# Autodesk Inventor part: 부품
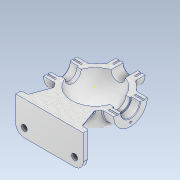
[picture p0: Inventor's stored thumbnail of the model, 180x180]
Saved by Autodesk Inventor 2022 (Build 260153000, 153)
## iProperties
Created: 2024-04
Part Number: 부품
Material: 알루미늄 6061
Document SubType Name: Modeling
Designer: admin
Density: 2.7 g/cm^3
Appearance: 알루미늄 - 평지
Mass: 2352.45 g
Surface Area: 1021.09 cm^2
Volume: 871.277 cm^3
Author: admin
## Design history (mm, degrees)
sketch "스케치1"
  geometry: L1 (-154.368, 0)-(181.043, 0) reference; L2 (0, -46.839)-(0, 70.807) reference; L3 (-65, 31)-(65, 31); L4 (65, 31)-(65, 0); L5 (-65, 0)-(-65, 31); L6 (-65, 31)-(60.942, -29.064); L7 (65, 31)-(-62.972, -30.033); L8 (-106.452, 0)-(133.128, 0); A1 r 54 centre (0, 0) between (54, 0) and (-54, 0); 3 further points
  constraints: 12 end point, 8 point on line, 2 point on circle, 1 centre point, 1 coincident, 1 horizontal, 1 parallel, 1 perpendicular, 1 other
  dimensions: "d0" = 108 diameter of A1; "d1" = 130 distance of L3.start L3.end; "d2" = 62 diameter of L3 L8
revolve "회전1" stored, may be unused: angle "d3" = 360 deg
node "작업 평면1"
sketch "스케치3"
  geometry: L1 (-62.5, -62.5)-(62.5, -62.5); L2 (62.5, -62.5)-(62.5, 62.5); L3 (62.5, 62.5)-(-62.5, 62.5); L4 (-62.5, 62.5)-(-62.5, -62.5); L5 (-62.5, -62.5)-(62.5, 62.5); L6 (62.5, -62.5)-(-62.5, 62.5); 1 further point
  constraints: 12 end point, 2 midpoint, 2 parallel, 1 horizontal, 1 perpendicular
  dimensions: "d5" = 125 distance of L1.start L1.end; "d6" = 125 distance of L1.end L2.end
extrude "돌출1" join sketch "스케치3" distance "d7" = 10; taper "d8" = 0 deg
fillet "모깎기1" dims "d10" = 16
sketch "스케치5"
  geometry: L1 (-62.5, -46.5)-(-62.5, 46.5) reference; L2 (-46.5, 62.5)-(46.5, 62.5) reference; L3 (62.5, 46.5)-(62.5, -46.5) reference; L4 (46.5, -62.5)-(-46.5, -62.5) reference; L5 (0, -92.139)-(0, 92.139) reference; L6 (92.139, 0)-(-92.139, 0) reference; L7 (-50.5, 4)-(50.5, 4); L8 (50.5, 4)-(50.5, -4); L9 (50.5, -4)-(-50.5, -4); L10 (-50.5, -4)-(-50.5, 4); C1 r 5.5 at (-46.5, 46.5); C2 r 5.5 at (46.5, 46.5); C3 r 5.5 at (46.5, -46.5); C4 r 5.5 at (-46.5, -46.5); A1 r 16 centre (-46.5, -46.5) between (-62.5, -46.5) and (-46.5, -62.5) reference; A2 r 16 centre (-46.5, 46.5) between (-46.5, 62.5) and (-62.5, 46.5) reference; A3 r 16 centre (46.5, 46.5) between (62.5, 46.5) and (46.5, 62.5) reference; A4 r 16 centre (46.5, -46.5) between (46.5, -62.5) and (62.5, -46.5) reference; 1 further point
  constraints: 8 end point, 4 centre point, 4 coincident, 3 equal radius, 2 parallel, 1 horizontal, 1 perpendicular, 2 other
  dimensions: "d11" = 11 diameter of C1; "d12" = 8 distance of L7.end L8.end; "d14" = 12 distance between parallel lines of L3 L8
extrude "돌출2" join sketch "스케치5" stored distance "d15" = 10; taper "d16" = 0 deg
feature "면 기울기1" dims angle "d17" = 20 deg
feature "면 기울기2" dims angle "d18" = 20 deg
sketch "스케치7"
  geometry: L1 (-50.5, 75)-(-36.114, 35.475); L2 (-62.5, 85)-(-62.5, 75) reference; L3 (-46.5, 75)-(-62.5, 75) reference; 1 further point
  constraints: 2 end point, 1 point on line
  dimensions: "d19" = 12 distance from line of L2 L1.start; "d20" = 110 deg angle of L3 L1
feature "리브1" sketch "스케치7" dims "d21" = 1, "d22" = 8, "d23" = 0, "d24" = 0, "d25" = 1, "d26" = 1
node "작업 평면2"
sketch "스케치8"
  geometry: C1 r 27 at (0, 0); 1 further point
  constraints: 1 centre point, 1 coincident
  dimensions: "d28" = 54 diameter of C1
extrude "돌출3" join sketch "스케치8" stored distance "d29" = 10; taper "d30" = 0 deg
sketch "스케치9"
  geometry: L1 (0, -87.5)-(0, 87.5) reference; L2 (91, 0)-(-91, 0) reference; C1 r 27 at (0, 0) reference; A1 r 20 centre (0, 0) between (20, 0) and (0, 20); 3 further points
  constraints: 4 point on circle, 4 point on line, 1 centre point, 1 coincident
  dimensions: "d31" = 40 diameter of A1
hole "구멍1" sketch "스케치9" at (20, 0), (0, 20), (-20, 0), (0, -20) diameter "d32" = 3.242; stored, may be unused: countersink angle "d36" = 90 deg, drill point angle "d38" = 118 deg; dims "d33" = 9, "d34" = 4, "d35" = 2, "d37" = 11
node "작업 평면3"
node "작업 평면4"
node "작업 평면5"
sketch "스케치12"
  geometry: L1 (0, -75.6)-(0, 75.6) reference; L2 (-75.6, 0)-(75.6, 0) reference; A1 r 24 centre (0, 0) between (-24, 0) and (0, 24); 3 further points
  constraints: 4 point on circle, 4 point on line, 1 centre point, 1 coincident
  dimensions: "d46" = 48 diameter of A1
hole "구멍2" sketch "스케치12" at (-24, 0), (0, 24), (24, 0), (0, -24) diameter "d47" = 3.242; stored, may be unused: countersink angle "d51" = 90 deg, drill point angle "d53" = 118 deg; dims "d48" = 12, "d49" = 4, "d50" = 2, "d52" = 15
sketch "스케치13"
  geometry: C1 r 17.5 at (0, 0); 1 further point
  constraints: 1 centre point, 1 coincident
  dimensions: "d54" = 35 diameter of C1
extrude "돌출5" cut sketch "스케치13" distance "d55" = 16; taper "d56" = 0 deg
sketch "스케치14"
  geometry: C1 r 15 at (0, 0); 1 further point
  constraints: 1 centre point, 1 coincident
  dimensions: "d57" = 30 diameter of C1
extrude "돌출6" cut sketch "스케치14" stored distance "d58" = 16; taper "d59" = 0 deg
fillet "모깎기2" dims "d60" = 0.6
fillet "모깎기3" dims "d63" = 3
fillet "모깎기4" dims "d64" = 3
fillet "모깎기5" dims "d65" = 3
node "작업 평면6"
sketch "스케치17"
  geometry: L1 (27, -65)-(-27, -65) reference; 3 further points
  constraints: 1 midpoint, 1 vertical alignment, 1 other
  dimensions: "d69" = 9 distance from line of point (0, -56) L1
feature "엠보싱1" sketch "스케치17" dims "d67" = 0.5, "d68" = 0
sketch "스케치19"
  geometry: C1 r 13 at (0, 0); 1 further point
  constraints: 1 centre point, 1 coincident
  dimensions: "d71" = 26 diameter of C1
extrude "돌출7" cut sketch "스케치19" stored distance "d72" = 10; taper "d73" = 0 deg
sketch "스케치21"
  geometry: 1 further point
chamfer "모따기1" distance "d75" = 1; stored, may be unused: second distance "d76" = 2, angle "d77" = 45 deg
sketch "스케치23"
  geometry: C1 r 5.5 at (-46.5, -46.5); C2 r 5.5 at (-46.5, 46.5); C3 r 5.5 at (46.5, 46.5); C4 r 5.5 at (46.5, -46.5); A1 r 13 centre (-46.5, -46.5) between (-59.5, -46.5) and (-46.5, -59.5) reference; A2 r 13 centre (-46.5, 46.5) between (-46.5, 59.5) and (-59.5, 46.5) reference; A3 r 13 centre (46.5, 46.5) between (59.5, 46.5) and (46.5, 59.5) reference; A4 r 13 centre (46.5, -46.5) between (46.5, -59.5) and (59.5, -46.5) reference; 1 further point
  constraints: 4 centre point, 4 coincident, 3 equal radius
  dimensions: "d79" = 11 diameter of C1
extrude "돌출8" cut sketch "스케치23" extent not by distance; stored distance "d80" = 10; taper "d81" = 0 deg
sketch "스케치25"
  geometry: L1 (-112.129, 0)-(130.935, 0); L2 (44, 0)-(-44, 0); L3 (-45.749, -31)-(-45.749, 31) reference; A1 r 44 centre (0, 0) between (-44, 0) and (44, 0); 2 further points
  constraints: 4 end point, 2 point on circle, 2 point on line, 1 centre point, 1 coincident, 1 horizontal, 1 midpoint, 1 perpendicular
  dimensions: "d83" = 44 radius of A1
revolve "회전2" sketch "스케치25" stored, may be unused: angle "d84" = 90 deg
node "솔리드1"
mirror "미러1"
mirror "미러2"
node "투영된 루프1"
feature "A9D066F2-1C7D-4E18-AEED-F7BC21143FA4" dims "d32" = 3.242, "d33" = 9, "d34" = 4, "d35" = 2, "d36" = 90 deg, "d37" = 11, "d38" = 118 deg
other parameters: "d4" = 85, "d27" = -65, "d39" = -65, "d44" = -65, "d45" = 65, "d66" = 66
